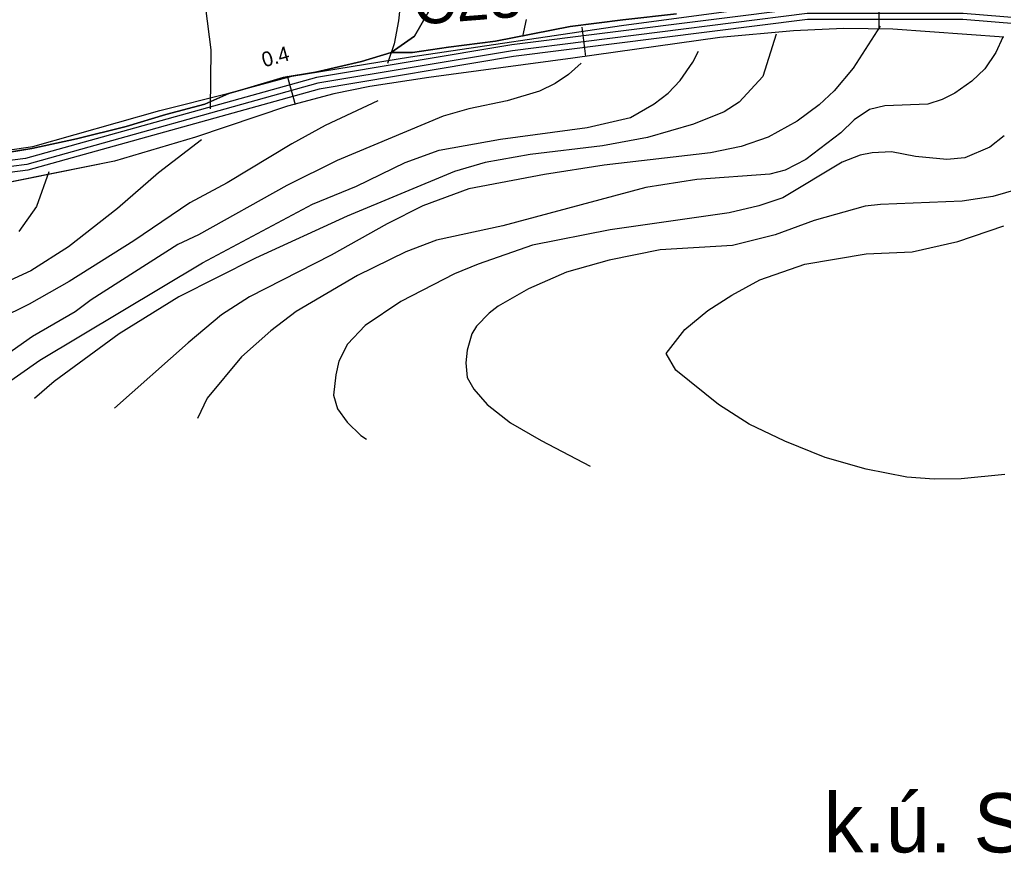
# Model space of a CAD drawing. Extents: x -662620 to -656370, y -1067090 to -1062990.
# Drawn here: x -659010.6 to -658679.2, y -1066673.1 to -1066386.4 of the extents above; entities that cross this region are included whole.
import ezdxf

# ---------------------------------------------------------------- set-up
doc = ezdxf.new("R2010")
doc.units = 0
for name, color, linetype in [('Default', 7, 'Continuous'), ('HRANICE_KATASTRÁLNÍHO_ÚZEMÍ', 7, 'Continuous'), ('NÁZEV_K__Ú_', 7, 'Continuous'), ('OBVOD_PÚ', 7, 'Continuous'), ('ORNÁ_PŮDA_-_STÁVAJÍCÍ', 7, 'Continuous'), ('OSTATNÍ_PLOCHA_-_STÁVAJÍCÍ', 7, 'Continuous'), ('OVOCNÝ_SAD_-_STÁVAJÍCÍ', 7, 'Continuous'), ('POLNÍ_CESTA_STÁVAJÍCÍ_-_KRAJ', 7, 'Continuous'), ('POLNÍ_CESTA_STÁVAJÍCÍ_-_OSA', 7, 'Continuous'), ('Popis_objektú_polních_cest_stávajících', 7, 'Continuous'), ('VRSTEVNICE_ZDŮRAZNĚNÁ', 7, 'Continuous'), ('VRSTEVNICE_ZÁKLADNÍ', 7, 'Continuous')]:
    doc.layers.add(name, color=color, linetype=linetype)

msp = doc.modelspace()

# ---------------------------------------------------------------- linework, layer by layer
at = {"layer": 'HRANICE_KATASTRÁLNÍHO_ÚZEMÍ'}
msp.add_lwpolyline([(-659053.57, -1066436), (-659006.19, -1066429.15), (-658963.47, -1066417.01), (-658940.11, -1066411.15), (-658918.93, -1066405.4), (-658878.94, -1066398.9), (-658807.8, -1066388.34), (-658763.27, -1066382.42)], dxfattribs=at)
at = {"layer": 'OBVOD_PÚ'}
for points in [[(-658733.02, -1066389.36), (-658749.84, -1066390.18)], [(-658716.35, -1066389.62), (-658733.02, -1066389.36)], [(-658679.01, -1066392.28), (-658716.35, -1066389.62)], [(-658774.71, -1066392.34), (-658824.19, -1066399.4)], [(-658749.84, -1066390.18), (-658774.71, -1066392.34)], [(-658824.19, -1066399.4), (-658872.72, -1066405.85)], [(-658872.72, -1066405.85), (-658892.65, -1066408.86)], [(-658892.65, -1066408.86), (-658904.75, -1066411.35)], [(-658904.75, -1066411.35), (-658920.43, -1066415.53)], [(-658920.43, -1066415.53), (-658951.45, -1066426.03)], [(-658951.45, -1066426.03), (-658978.73, -1066434.12)], [(-658978.73, -1066434.12), (-659034.87, -1066445.35)]]:
    msp.add_lwpolyline(points, dxfattribs=at)
at = {"layer": 'ORNÁ_PŮDA_-_STÁVAJÍCÍ'}
for p, q in [((-658871.22, -1066380.79), (-658877.55, -1066391.99)), ((-658877.55, -1066391.99), (-658885.43, -1066397.47)), ((-658885.43, -1066397.47), (-658895.5, -1066400.43)), ((-658895.5, -1066400.43), (-658910.94, -1066404.02)), ((-658921.81, -1066405.88), (-658933.86, -1066409.42)), ((-658910.94, -1066404.02), (-658921.81, -1066405.88)), ((-658933.86, -1066409.42), (-658940.12, -1066411.23)), ((-658940.12, -1066411.23), (-658948.27, -1066414.88)), ((-658948.27, -1066414.88), (-658961.45, -1066418.31)), ((-658961.45, -1066418.31), (-658974.74, -1066422.34)), ((-658974.74, -1066422.34), (-658991.54, -1066426.5)), ((-658991.54, -1066426.5), (-659006.52, -1066429.83)), ((-659006.52, -1066429.83), (-659025.95, -1066432.95))]:
    msp.add_line(p, q, dxfattribs=at)
msp.add_lwpolyline([(-658871.22, -1066380.79), (-658877.55, -1066391.99), (-658885.43, -1066397.47), (-658895.5, -1066400.43), (-658910.94, -1066404.02), (-658921.81, -1066405.88), (-658933.86, -1066409.42), (-658940.12, -1066411.23), (-658948.27, -1066414.88), (-658961.45, -1066418.31), (-658974.74, -1066422.34), (-658991.54, -1066426.5), (-659006.52, -1066429.83), (-659025.95, -1066432.95)], dxfattribs=at)
at = {"layer": 'OSTATNÍ_PLOCHA_-_STÁVAJÍCÍ'}
for p, q in [((-658825.13, -1066388.7), (-658807.43, -1066386.38)), ((-658825.13, -1066388.7), (-658807.43, -1066386.38)), ((-658807.43, -1066386.38), (-658789.25, -1066384.41)), ((-658807.43, -1066386.38), (-658789.25, -1066384.41)), ((-658850.32, -1066393.67), (-658825.13, -1066388.7)), ((-658850.32, -1066393.67), (-658825.13, -1066388.7)), ((-658733.02, -1066389.36), (-658749.84, -1066390.18)), ((-658733.02, -1066389.36), (-658749.84, -1066390.18)), ((-658716.35, -1066389.62), (-658733.02, -1066389.36)), ((-658716.35, -1066389.62), (-658733.02, -1066389.36)), ((-658679.01, -1066392.28), (-658716.35, -1066389.62)), ((-658679.01, -1066392.28), (-658716.35, -1066389.62)), ((-658774.71, -1066392.34), (-658824.19, -1066399.4)), ((-658774.71, -1066392.34), (-658824.19, -1066399.4)), ((-658749.84, -1066390.18), (-658774.71, -1066392.34)), ((-658749.84, -1066390.18), (-658774.71, -1066392.34)), ((-658878.23, -1066397.41), (-658866.19, -1066395.61)), ((-658878.23, -1066397.41), (-658866.19, -1066395.61)), ((-658866.19, -1066395.61), (-658850.32, -1066393.67)), ((-658866.19, -1066395.61), (-658850.32, -1066393.67)), ((-658895.5, -1066400.43), (-658885.43, -1066397.47)), ((-658895.5, -1066400.43), (-658885.43, -1066397.47)), ((-658885.43, -1066397.47), (-658878.23, -1066397.41)), ((-658885.43, -1066397.47), (-658878.23, -1066397.41)), ((-658824.19, -1066399.4), (-658872.72, -1066405.85)), ((-658824.19, -1066399.4), (-658872.72, -1066405.85)), ((-658910.94, -1066404.02), (-658895.5, -1066400.43)), ((-658910.94, -1066404.02), (-658895.5, -1066400.43)), ((-658933.86, -1066409.42), (-658921.81, -1066405.88)), ((-658933.86, -1066409.42), (-658921.81, -1066405.88)), ((-658921.81, -1066405.88), (-658910.94, -1066404.02)), ((-658921.81, -1066405.88), (-658910.94, -1066404.02)), ((-658872.72, -1066405.85), (-658892.65, -1066408.86)), ((-658872.72, -1066405.85), (-658892.65, -1066408.86)), ((-658940.12, -1066411.23), (-658933.86, -1066409.42)), ((-658940.12, -1066411.23), (-658933.86, -1066409.42)), ((-658892.65, -1066408.86), (-658904.75, -1066411.35)), ((-658892.65, -1066408.86), (-658904.75, -1066411.35)), ((-658948.27, -1066414.88), (-658940.12, -1066411.23)), ((-658948.27, -1066414.88), (-658940.12, -1066411.23)), ((-658904.75, -1066411.35), (-658920.43, -1066415.53)), ((-658904.75, -1066411.35), (-658920.43, -1066415.53)), ((-658961.45, -1066418.31), (-658948.27, -1066414.88)), ((-658961.45, -1066418.31), (-658948.27, -1066414.88)), ((-658920.43, -1066415.53), (-658951.45, -1066426.03)), ((-658920.43, -1066415.53), (-658951.45, -1066426.03)), ((-658974.74, -1066422.34), (-658961.45, -1066418.31)), ((-658974.74, -1066422.34), (-658961.45, -1066418.31)), ((-658991.54, -1066426.5), (-658974.74, -1066422.34)), ((-658991.54, -1066426.5), (-658974.74, -1066422.34)), ((-658951.45, -1066426.03), (-658978.73, -1066434.12)), ((-658951.45, -1066426.03), (-658978.73, -1066434.12)), ((-659006.52, -1066429.83), (-658991.54, -1066426.5)), ((-659006.52, -1066429.83), (-658991.54, -1066426.5)), ((-659025.95, -1066432.95), (-659006.52, -1066429.83)), ((-659025.95, -1066432.95), (-659006.52, -1066429.83)), ((-658978.73, -1066434.12), (-659034.87, -1066445.35)), ((-658978.73, -1066434.12), (-659034.87, -1066445.35))]:
    msp.add_line(p, q, dxfattribs=at)
for points in [[(-659025.95, -1066432.95), (-659006.52, -1066429.83), (-658991.54, -1066426.5), (-658974.74, -1066422.34), (-658961.45, -1066418.31), (-658948.27, -1066414.88), (-658940.12, -1066411.23), (-658933.86, -1066409.42), (-658921.81, -1066405.88), (-658910.94, -1066404.02), (-658895.5, -1066400.43), (-658885.43, -1066397.47), (-658878.23, -1066397.41), (-658866.19, -1066395.61), (-658850.32, -1066393.67), (-658825.13, -1066388.7), (-658807.43, -1066386.38), (-658789.25, -1066384.41)], [(-659025.95, -1066432.95), (-659006.52, -1066429.83), (-658991.54, -1066426.5), (-658974.74, -1066422.34), (-658961.45, -1066418.31), (-658948.27, -1066414.88), (-658940.12, -1066411.23), (-658933.86, -1066409.42), (-658921.81, -1066405.88), (-658910.94, -1066404.02), (-658895.5, -1066400.43), (-658885.43, -1066397.47), (-658878.23, -1066397.41), (-658866.19, -1066395.61), (-658850.32, -1066393.67), (-658825.13, -1066388.7), (-658807.43, -1066386.38), (-658789.25, -1066384.41)], [(-658679.01, -1066392.28), (-658716.35, -1066389.62), (-658733.02, -1066389.36), (-658749.84, -1066390.18), (-658774.71, -1066392.34), (-658824.19, -1066399.4), (-658872.72, -1066405.85), (-658892.65, -1066408.86), (-658904.75, -1066411.35), (-658920.43, -1066415.53), (-658951.45, -1066426.03), (-658978.73, -1066434.12), (-659034.87, -1066445.35)], [(-658679.01, -1066392.28), (-658716.35, -1066389.62), (-658733.02, -1066389.36), (-658749.84, -1066390.18), (-658774.71, -1066392.34), (-658824.19, -1066399.4), (-658872.72, -1066405.85), (-658892.65, -1066408.86), (-658904.75, -1066411.35), (-658920.43, -1066415.53), (-658951.45, -1066426.03), (-658978.73, -1066434.12), (-659034.87, -1066445.35)]]:
    msp.add_lwpolyline(points, dxfattribs=at)
at = {"layer": 'OVOCNÝ_SAD_-_STÁVAJÍCÍ'}
for p, q in [((-658877.55, -1066391.99), (-658871.22, -1066380.79)), ((-658807.43, -1066386.38), (-658825.13, -1066388.7)), ((-658789.25, -1066384.41), (-658807.43, -1066386.38)), ((-658825.13, -1066388.7), (-658850.32, -1066393.67)), ((-658885.43, -1066397.47), (-658877.55, -1066391.99)), ((-658866.19, -1066395.61), (-658878.23, -1066397.41)), ((-658850.32, -1066393.67), (-658866.19, -1066395.61)), ((-658878.23, -1066397.41), (-658885.43, -1066397.47))]:
    msp.add_line(p, q, dxfattribs=at)
msp.add_lwpolyline([(-658789.25, -1066384.41), (-658807.43, -1066386.38), (-658825.13, -1066388.7), (-658850.32, -1066393.67), (-658866.19, -1066395.61), (-658878.23, -1066397.41), (-658885.43, -1066397.47), (-658877.55, -1066391.99), (-658871.22, -1066380.79)], dxfattribs=at)
at = {"layer": 'POLNÍ_CESTA_STÁVAJÍCÍ_-_KRAJ'}
for points in [[(-658524.77, -1066416.91), (-658585.14, -1066399.5), (-658627.95, -1066387.63), (-658692.63, -1066382.35), (-658745.41, -1066382.35), (-658844.82, -1066394.86), (-658910.58, -1066405.85), (-659008.67, -1066433.22), (-659055.89, -1066439.26), (-659092.46, -1066437.38), (-659149.26, -1066425.87), (-659161.27, -1066431.66), (-659178.7, -1066451.74), (-659206.01, -1066461.71), (-659282.28, -1066460.95), (-659319.31, -1066453.29)], [(-658525.87, -1066420.75), (-658586.23, -1066403.35), (-658628.66, -1066391.58), (-658692.79, -1066386.35), (-658745.16, -1066386.35), (-658844.24, -1066398.82), (-658909.71, -1066409.76), (-659007.88, -1066437.15), (-659055.74, -1066443.28), (-659092.96, -1066441.36), (-659148.74, -1066430.05), (-659158.79, -1066434.91), (-659176.35, -1066455.14), (-659205.33, -1066465.71), (-659282.71, -1066464.95), (-659320.12, -1066457.21)]]:
    msp.add_lwpolyline(points, dxfattribs=at)
at = {"layer": 'POLNÍ_CESTA_STÁVAJÍCÍ_-_OSA'}
for points in [[(-658721.04, -1066389.35), (-658721.04, -1066379.35)], [(-658525.32, -1066418.83), (-658585.69, -1066401.42), (-658628.3, -1066389.61), (-658692.71, -1066384.35), (-658745.29, -1066384.35), (-658844.53, -1066396.84), (-658910.15, -1066407.8), (-659008.28, -1066435.19), (-659055.82, -1066441.27), (-659092.71, -1066439.37), (-659149, -1066427.96), (-659160.03, -1066433.28), (-659177.52, -1066453.44), (-659205.67, -1066463.71), (-659282.5, -1066462.95), (-659319.71, -1066455.25)], [(-658819.82, -1066398.77), (-658821.07, -1066388.85)], [(-658917.66, -1066415.09), (-658920.35, -1066405.46)]]:
    msp.add_lwpolyline(points, dxfattribs=at)
at = {"layer": 'VRSTEVNICE_ZDŮRAZNĚNÁ'}
for points in [[(-658976.37, -1066265.56), (-658968.63, -1066289.92), (-658955.01, -1066348.39), (-658947.99, -1066382.5), (-658946.27, -1066396.55), (-658946.42, -1066416.47)], [(-658755.7, -1066391.22), (-658760.17, -1066405.53), (-658768.13, -1066414.18), (-658773.29, -1066417.47), (-658783.61, -1066421.63), (-658799.09, -1066426.07), (-658814.28, -1066428.94), (-658838.64, -1066431.8), (-658853.83, -1066434.53), (-658864.15, -1066437.54), (-658900.27, -1066452.58), (-658931.22, -1066466.77), (-658957.02, -1066479.81), (-658977.09, -1066492.28), (-658999.01, -1066508.33), (-659005.61, -1066514.11)], [(-659000.86, -1066437.65), (-659005.01, -1066449.31), (-659010.91, -1066457.74)], [(-658678.7, -1066539.72), (-658693.32, -1066541.15), (-658702.49, -1066541.3), (-658711.66, -1066540.58), (-658725.42, -1066537.86), (-658739.18, -1066533.99), (-658752.79, -1066528.4), (-658764.83, -1066522.67), (-658775.15, -1066516.07), (-658789.48, -1066504.46), (-658792.78, -1066498.88), (-658786.47, -1066490.85), (-658778.73, -1066484.4), (-658770.71, -1066479.24), (-658761.25, -1066474.08), (-658746.06, -1066468.78), (-658725.42, -1066465.34), (-658709.94, -1066464.62), (-658694.46, -1066461.18), (-658678.99, -1066455.88)]]:
    msp.add_lwpolyline(points, dxfattribs=at)
at = {"layer": 'VRSTEVNICE_ZÁKLADNÍ'}
for points in [[(-658881.92, -1066376.2), (-658883.02, -1066386.8), (-658884.5, -1066394.54), (-658886.73, -1066401.13)], [(-658881.92, -1066376.2), (-658883.02, -1066386.8), (-658884.5, -1066394.54), (-658886.73, -1066401.13)], [(-658839.94, -1066386.35), (-658841.22, -1066392.1)], [(-658839.94, -1066386.35), (-658841.22, -1066392.1)], [(-658720.65, -1066388.61), (-658729.72, -1066402.71), (-658736.17, -1066410.31), (-658741.19, -1066415.04), (-658748.64, -1066420.62), (-658758.38, -1066425.93), (-658767.56, -1066429.08), (-658777.87, -1066431.23), (-658813.7, -1066435.39), (-658833.77, -1066438.54), (-658859.28, -1066443.41), (-658874.76, -1066449.14), (-658886.8, -1066455.16), (-658905.71, -1066465.77), (-658933.23, -1066479.81), (-658942.69, -1066485.83), (-658953.9, -1066495.33), (-658978.73, -1066517.38)], [(-658720.65, -1066388.61), (-658729.72, -1066402.71), (-658736.17, -1066410.31), (-658741.19, -1066415.04), (-658748.64, -1066420.62), (-658758.38, -1066425.93), (-658767.56, -1066429.08), (-658777.87, -1066431.23), (-658813.7, -1066435.39), (-658833.77, -1066438.54), (-658859.28, -1066443.41), (-658874.76, -1066449.14), (-658886.8, -1066455.16), (-658905.71, -1066465.77), (-658933.23, -1066479.81), (-658942.69, -1066485.83), (-658953.9, -1066495.33), (-658978.73, -1066517.38)], [(-658679.32, -1066392.32), (-658681.71, -1066397.41), (-658685.44, -1066403), (-658689.74, -1066407.15), (-658695.47, -1066411.17), (-658699.77, -1066413.32), (-658704.64, -1066414.89), (-658719.11, -1066415.47), (-658724.27, -1066416.61), (-658729.43, -1066420.19), (-658733.88, -1066424.49), (-658745.77, -1066433.52), (-658752.65, -1066437.11), (-658757.81, -1066438.4), (-658782.46, -1066440.26), (-658799.66, -1066442.98), (-658847.81, -1066455.88), (-658870.17, -1066460.75), (-658880.49, -1066464.62), (-658896.83, -1066472.65), (-658917.47, -1066484.69), (-658926.06, -1066491.28), (-658935.95, -1066500.02), (-658947.42, -1066513.92), (-658950.68, -1066520.8)], [(-658679.32, -1066392.32), (-658681.71, -1066397.41), (-658685.44, -1066403), (-658689.74, -1066407.15), (-658695.47, -1066411.17), (-658699.77, -1066413.32), (-658704.64, -1066414.89), (-658719.11, -1066415.47), (-658724.27, -1066416.61), (-658729.43, -1066420.19), (-658733.88, -1066424.49), (-658745.77, -1066433.52), (-658752.65, -1066437.11), (-658757.81, -1066438.4), (-658782.46, -1066440.26), (-658799.66, -1066442.98), (-658847.81, -1066455.88), (-658870.17, -1066460.75), (-658880.49, -1066464.62), (-658896.83, -1066472.65), (-658917.47, -1066484.69), (-658926.06, -1066491.28), (-658935.95, -1066500.02), (-658947.42, -1066513.92), (-658950.68, -1066520.8)], [(-659017.93, -1066510.91), (-659003.89, -1066501.17), (-658949, -1066468.35), (-658912.02, -1066448.57), (-658897.11, -1066442.55), (-658880.78, -1066434.53), (-658869.31, -1066430.37), (-658848.67, -1066426.64), (-658819.44, -1066422.77), (-658804.82, -1066419.33), (-658796.79, -1066414.75), (-658792.06, -1066411.17), (-658788.05, -1066406.87), (-658783.77, -1066400.71), (-658781.89, -1066396.95)], [(-659017.93, -1066510.91), (-659003.89, -1066501.17), (-658949, -1066468.35), (-658912.02, -1066448.57), (-658897.11, -1066442.55), (-658880.78, -1066434.53), (-658869.31, -1066430.37), (-658848.67, -1066426.64), (-658819.44, -1066422.77), (-658804.82, -1066419.33), (-658796.79, -1066414.75), (-658792.06, -1066411.17), (-658788.05, -1066406.87), (-658783.77, -1066400.71), (-658781.89, -1066396.95)], [(-658821.48, -1066401.04), (-658825.75, -1066404.86), (-658830.22, -1066407.91), (-658835.49, -1066410.45), (-658846.38, -1066413.75), (-658859.28, -1066416.47), (-658867.88, -1066418.9), (-658903.71, -1066433.81), (-658920.62, -1066442.27), (-658950.43, -1066458.89), (-658957.31, -1066462.19), (-658986.54, -1066480.82), (-658991.99, -1066484.83), (-659006.32, -1066493.14), (-659026.67, -1066507.47)], [(-658821.48, -1066401.04), (-658825.75, -1066404.86), (-658830.22, -1066407.91), (-658835.49, -1066410.45), (-658846.38, -1066413.75), (-658859.28, -1066416.47), (-658867.88, -1066418.9), (-658903.71, -1066433.81), (-658920.62, -1066442.27), (-658950.43, -1066458.89), (-658957.31, -1066462.19), (-658986.54, -1066480.82), (-658991.99, -1066484.83), (-659006.32, -1066493.14), (-659026.67, -1066507.47)], [(-658889.92, -1066413.74), (-658907.72, -1066422.06), (-658918.9, -1066428.22), (-658940.68, -1066441.41), (-658953.29, -1066448.14), (-658972.21, -1066460.9), (-658994, -1066474.65), (-659007.47, -1066482.25), (-659017.79, -1066487.27)], [(-658889.92, -1066413.74), (-658907.72, -1066422.06), (-658918.9, -1066428.22), (-658940.68, -1066441.41), (-658953.29, -1066448.14), (-658972.21, -1066460.9), (-658994, -1066474.65), (-659007.47, -1066482.25), (-659017.79, -1066487.27)], [(-658678.84, -1066425.5), (-658683.72, -1066429.37), (-658692.17, -1066432.95), (-658698.19, -1066433.52), (-658708.8, -1066432.52), (-658716.9, -1066430.94), (-658723.41, -1066431.23), (-658727.43, -1066432.09), (-658733.45, -1066434.38), (-658753.51, -1066446.42), (-658761.54, -1066449.14), (-658771.57, -1066451.44), (-658811.7, -1066457.17), (-658837.78, -1066462.33), (-658856.13, -1066468.78), (-658864.15, -1066472.08), (-658882.21, -1066481.39), (-658894.25, -1066489.42), (-658900.12, -1066495.72), (-658903.13, -1066501.46), (-658904.14, -1066506.04), (-658904.85, -1066512.92), (-658903.56, -1066517.51), (-658900.27, -1066522.09), (-658895.68, -1066526.54), (-658893.77, -1066527.74)], [(-658678.84, -1066425.5), (-658683.72, -1066429.37), (-658692.17, -1066432.95), (-658698.19, -1066433.52), (-658708.8, -1066432.52), (-658716.9, -1066430.94), (-658723.41, -1066431.23), (-658727.43, -1066432.09), (-658733.45, -1066434.38), (-658753.51, -1066446.42), (-658761.54, -1066449.14), (-658771.57, -1066451.44), (-658811.7, -1066457.17), (-658837.78, -1066462.33), (-658856.13, -1066468.78), (-658864.15, -1066472.08), (-658882.21, -1066481.39), (-658894.25, -1066489.42), (-658900.12, -1066495.72), (-658903.13, -1066501.46), (-658904.14, -1066506.04), (-658904.85, -1066512.92), (-658903.56, -1066517.51), (-658900.27, -1066522.09), (-658895.68, -1066526.54), (-658893.77, -1066527.74)], [(-658949.38, -1066426.93), (-658963.9, -1066437.97), (-658977.66, -1066450), (-658994.14, -1066462.9), (-659006.89, -1066471.07), (-659016.93, -1066475.66)], [(-658949.38, -1066426.93), (-658963.9, -1066437.97), (-658977.66, -1066450), (-658994.14, -1066462.9), (-659006.89, -1066471.07), (-659016.93, -1066475.66)], [(-658674.11, -1066443.56), (-658682.71, -1066445.99), (-658693.03, -1066447.57), (-658720.55, -1066448.71), (-658725.71, -1066449.29), (-658742.91, -1066454.02), (-658756.09, -1066458.89), (-658770.42, -1066462.47), (-658794.79, -1066463.91), (-658811.98, -1066467.49), (-658826.32, -1066471.5), (-658839.21, -1066477.09), (-658849.39, -1066482.97), (-658852.4, -1066485.26), (-658856.7, -1066489.7), (-658858.28, -1066492.28), (-658859.82, -1066497.77), (-658860.28, -1066502.03), (-658859.85, -1066507.04), (-658857.56, -1066510.91), (-658853.12, -1066516.07), (-658845.23, -1066522.24), (-658834.92, -1066528.26), (-658818.44, -1066536.92)], [(-658674.11, -1066443.56), (-658682.71, -1066445.99), (-658693.03, -1066447.57), (-658720.55, -1066448.71), (-658725.71, -1066449.29), (-658742.91, -1066454.02), (-658756.09, -1066458.89), (-658770.42, -1066462.47), (-658794.79, -1066463.91), (-658811.98, -1066467.49), (-658826.32, -1066471.5), (-658839.21, -1066477.09), (-658849.39, -1066482.97), (-658852.4, -1066485.26), (-658856.7, -1066489.7), (-658858.28, -1066492.28), (-658859.82, -1066497.77), (-658860.28, -1066502.03), (-658859.85, -1066507.04), (-658857.56, -1066510.91), (-658853.12, -1066516.07), (-658845.23, -1066522.24), (-658834.92, -1066528.26), (-658818.44, -1066536.92)]]:
    msp.add_lwpolyline(points, dxfattribs=at)

# ---------------------------------------------------------------- texts
at = {"layer": 'Default'}
msp.add_text('0.4', height=5, rotation=15.5928, dxfattribs=at).set_placement((-658928.29, -1066402.48))
at = {"layer": 'NÁZEV_K__Ú_'}
msp.add_text('k.ú. Svinčany', height=20, dxfattribs=at).set_placement((-658739.69, -1066667.07))
at = {"layer": 'Popis_objektú_polních_cest_stávajících'}
msp.add_text('C23', height=15, rotation=4.5, dxfattribs=at).set_placement((-658877.68, -1066388.18))

doc.saveas('drawing.dxf')
